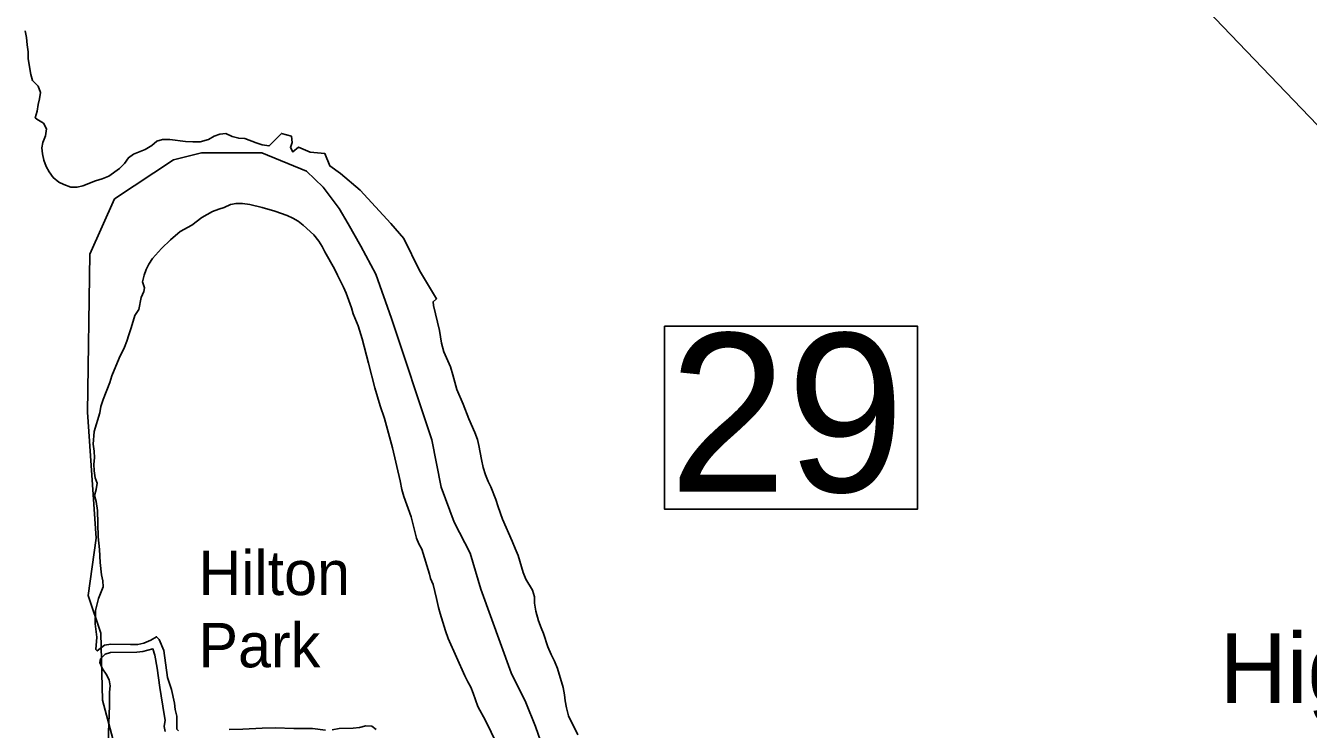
# Model space of a CAD drawing. Extents: x 1945482 to 2853149, y 66427 to 1015778.
# Drawn here: x 2317928 to 2321253, y 188516 to 190339 of the extents above; entities that cross this region are included whole.
import ezdxf

# ---------------------------------------------------------------- set-up
doc = ezdxf.new("R2010")
doc.units = 0
for name, color, linetype in [('Old_Level_19', 7, 'Continuous'), ('Old_Level_31', 7, 'Continuous'), ('Old_Level_48', 7, 'Continuous'), ('Old_Level_49', 7, 'Continuous'), ('Old_Level_56', 7, 'Continuous'), ('Old_Level_60', 7, 'Continuous'), ('Old_Level_9', 7, 'Continuous')]:
    doc.layers.add(name, color=color, linetype=linetype)

msp = doc.modelspace()

# ---------------------------------------------------------------- linework, layer by layer
at = {"layer": 'Old_Level_31'}
msp.add_lwpolyline([(2319584, 189560.5), (2320239.8, 189560.5), (2320239.8, 189086.6), (2319584, 189086.6)], close=True, dxfattribs=at)
at = {"layer": 'Old_Level_48'}
for points in [[(2317989.2, 186500.3), (2317987.1, 186775.2), (2318022.2, 187031.4), (2317993.3, 187312.5), (2318018.1, 187527.5), (2318092.5, 187707.3), (2318112.7, 187811), (2318144.1, 188046.3), (2318179.2, 188201.3), (2318181.3, 188391.4), (2318127.6, 188591.9), (2318123.4, 188765.5), (2318090.4, 188862.7), (2318111.1, 189011.5), (2318088.3, 189338), (2318094.5, 189747.3), (2318158.6, 189889.9), (2318311.4, 189991.1), (2318383.7, 190009.7)], [(2318383.7, 190009.7), (2318540.7, 190009.7), (2318656.4, 189962.2), (2318699.8, 189920.9), (2318741.3, 189865.1), (2318763.8, 189825.8), (2318796.9, 189767.9), (2318835.7, 189694.9), (2318876.2, 189580.4), (2318912.5, 189471.8), (2318944.4, 189375.1), (2318980.7, 189266.5), (2319005.5, 189143.7), (2319038.6, 189052.8), (2319080.4, 188972.3), (2319108.1, 188879.4), (2319186.7, 188662.5)], [(2319186.7, 188662.5), (2319224.5, 188585.7), (2319249.3, 188523.7), (2319281.9, 188432.2)]]:
    msp.add_lwpolyline(points, dxfattribs=at)
at = {"layer": 'Old_Level_49'}
for points in [[(2317989.2, 186500.3), (2317987.1, 186775.2), (2318022.2, 187031.4), (2317993.3, 187312.5), (2318018.1, 187527.5), (2318092.5, 187707.3), (2318112.7, 187811), (2318144.1, 188046.3), (2318179.2, 188201.3), (2318181.3, 188391.4), (2318127.6, 188591.9), (2318123.4, 188765.5), (2318090.4, 188862.7), (2318111.1, 189011.5), (2318088.3, 189338), (2318094.5, 189747.3), (2318158.6, 189889.9), (2318311.4, 189991.1), (2318383.7, 190009.7)], [(2318383.7, 190009.7), (2318540.7, 190009.7), (2318656.4, 189962.2), (2318699.8, 189920.9), (2318741.3, 189865.1), (2318763.8, 189825.8), (2318796.9, 189767.9), (2318835.7, 189694.9), (2318876.2, 189580.4), (2318912.5, 189471.8), (2318944.4, 189375.1), (2318980.7, 189266.5), (2319005.5, 189143.7), (2319038.6, 189052.8), (2319080.4, 188972.3), (2319108.1, 188879.4), (2319186.7, 188662.5)], [(2319186.7, 188662.5), (2319224.5, 188585.7), (2319249.3, 188523.7), (2319281.9, 188432.2)]]:
    msp.add_lwpolyline(points, dxfattribs=at)
at = {"layer": 'Old_Level_56'}
msp.add_lwpolyline([(2322518.1, 188787.6), (2320726, 190655.5), (2321161.7, 192135.8), (2321162.4, 192138.3)], dxfattribs=at)
at = {"layer": 'Old_Level_60'}
for points in [[(2317975.5, 189990.3), (2317971.7, 190006.6), (2317970.5, 190022.2), (2317973, 190036.2), (2317980, 190053.9), (2317982, 190071.9), (2317974.5, 190086.1), (2317957.5, 190096.6), (2317953.2, 190100.2), (2317958.5, 190117.7), (2317960.7, 190134.6), (2317964.5, 190149.2), (2317966.7, 190165.8), (2317961, 190181.9), (2317946, 190197), (2317942, 190212), (2317935, 190253.1), (2317934.5, 190270.8), (2317932.7, 190288.8), (2317930.2, 190308.4), (2317926.7, 190325.6)], [(2317975.5, 189990.3), (2317981.5, 189974.2), (2317989.2, 189960), (2318000, 189945.3), (2318014, 189933.8), (2318027.5, 189927.3), (2318045.5, 189920.8), (2318061.7, 189920.6), (2318076.5, 189924.3), (2318109, 189937.1), (2318126.5, 189942.5), (2318144, 189949.3), (2318171.5, 189968.8), (2318184.7, 189981.5), (2318194.7, 189996.8), (2318208, 190005.6), (2318238, 190018.5), (2318255, 190028.6), (2318268, 190039.7), (2318283, 190043.7), (2318302, 190043.6), (2318342.2, 190039), (2318361.5, 190037.8), (2318380.5, 190038.2), (2318402.5, 190043.9), (2318417.2, 190052.3), (2318431.5, 190057.6), (2318447, 190059.8), (2318463.5, 190051.7), (2318480.5, 190047.4), (2318496.2, 190046.5), (2318526, 190035.1), (2318541.7, 190030.3), (2318559.2, 190027.2), (2318591, 190059.7), (2318617, 190052.6), (2318619, 190036.4), (2318614.7, 190023.2), (2318621.2, 190012), (2318635.2, 190024.2), (2318665.7, 190011), (2318703.5, 190008), (2318716.5, 189975.5), (2318744.7, 189956.2), (2318795.5, 189912.5), (2318874.5, 189826.2), (2318908.2, 189787.6), (2318949.2, 189704.4), (2318993.5, 189631.7), (2318984.2, 189623.9), (2318985, 189614.4), (2319000.7, 189549.4), (2319006, 189516.4), (2319012, 189494.2), (2319029, 189454.8), (2319035.7, 189434.5), (2319045.7, 189396.2), (2319062.5, 189358.8), (2319077, 189320.8), (2319092.5, 189284.8), (2319099, 189266.7), (2319103, 189251.5), (2319109.5, 189215), (2319114.2, 189194.6), (2319120, 189175.9), (2319127.2, 189158), (2319134, 189144.3), (2319147, 189111.7), (2319153, 189092.3), (2319164.5, 189060.7), (2319189.5, 189004), (2319196.7, 188984.6), (2319204.5, 188966.8), (2319218, 188922.3), (2319224.5, 188905.1), (2319242.2, 188877), (2319247, 188859.2), (2319247.5, 188842.7), (2319250.7, 188822.1), (2319257.2, 188797.1), (2319264, 188778.9), (2319270.5, 188764.5), (2319282, 188729.8), (2319290.2, 188710.1)], [(2318773, 189607.8), (2318758.7, 189646), (2318752, 189661.8), (2318736.5, 189692.6), (2318729.2, 189708.9), (2318703.7, 189753), (2318697.2, 189766.6), (2318688.5, 189781), (2318675.5, 189797.5), (2318648, 189822.5), (2318635, 189832.4), (2318621.2, 189840.5), (2318606.5, 189847.1), (2318574.2, 189858.6), (2318541, 189867.9), (2318509, 189875.8), (2318490.2, 189878.4), (2318473.7, 189878.6), (2318459, 189875.3), (2318443.2, 189868.1), (2318428.7, 189863.6), (2318412.5, 189857.1), (2318385.2, 189841.7), (2318359, 189822.3), (2318328.7, 189805.6), (2318303.5, 189784.3), (2318280.2, 189761.5), (2318257, 189735.9), (2318247.5, 189721.1), (2318241, 189706.9)], [(2318110, 188723), (2318113.2, 188755.4), (2318108.2, 188789.8), (2318109.5, 188824), (2318117.2, 188855.4), (2318129.2, 188885.2), (2318128.5, 188901.2), (2318125.2, 188916.7), (2318121.2, 188948.7), (2318120, 188982.5), (2318116.5, 189015.3), (2318114.7, 189082.8), (2318111.5, 189106.1), (2318107, 189121.9), (2318111.2, 189137.2), (2318114, 189153.7), (2318108.7, 189167.9), (2318106, 189186.1), (2318105, 189202.8), (2318106.5, 189219.8), (2318105.5, 189237.2), (2318103.2, 189254.5), (2318105.7, 189288), (2318120.5, 189336), (2318123, 189352.1), (2318129.2, 189370.4), (2318146.7, 189415), (2318151.5, 189432.2), (2318170.5, 189477.6), (2318184.2, 189506), (2318191, 189521.8), (2318195.5, 189538.4), (2318201.7, 189556.3), (2318211, 189587.8), (2318221.5, 189603.3), (2318228, 189634.7), (2318235, 189650.1), (2318236.5, 189659.5), (2318231.5, 189675.4), (2318235.5, 189692.5), (2318241, 189706.9)], [(2319149.5, 188478.9), (2319119.7, 188539.6), (2319100.2, 188575.3), (2319088.5, 188609.9), (2319082, 188625.3), (2319074, 188639.2), (2319066.2, 188654.8), (2319023.5, 188751.5), (2319016.5, 188771.2), (2319002.5, 188816.2), (2318998, 188831.9), (2318993.5, 188854.9), (2318984.2, 188891.7), (2318977.2, 188906.9), (2318974.7, 188918.4), (2318955, 188982.7), (2318947.7, 188997), (2318941.7, 189011.3), (2318927.5, 189066.5), (2318908.5, 189119.3), (2318903.2, 189137.6), (2318899, 189159.8), (2318879, 189245), (2318858.5, 189321.6), (2318847, 189354.4), (2318833, 189401.2), (2318817.2, 189464.8), (2318800.2, 189527.9), (2318790.5, 189561), (2318777.5, 189592.9), (2318773, 189607.8)], [(2318110, 188723), (2318114, 188719.3), (2318133, 188734.3), (2318149.2, 188737.1), (2318200.2, 188735.9), (2318219, 188736.4), (2318234.7, 188739.7), (2318253, 188747.4), (2318267.5, 188756.2), (2318274.5, 188749.3), (2318286.5, 188720.6), (2318296.2, 188650.7), (2318306, 188619.4), (2318313.7, 188583.9), (2318316.2, 188567.8), (2318320, 188550.7), (2318320.5, 188517), (2318324.7, 188512.4)], [(2318290, 188510.8), (2318287, 188523.3), (2318289.7, 188539.7), (2318287.7, 188555.1), (2318276, 188624.5), (2318269, 188675.2), (2318263, 188708.5), (2318258, 188724.6), (2318231.7, 188718.1), (2318216.2, 188715.9), (2318148.2, 188715.1), (2318134, 188710.8), (2318122, 188699.3)], [(2318195.7, 188161.3), (2318195, 188176.8), (2318198.5, 188209.7), (2318196.7, 188264), (2318195.5, 188280.8), (2318183, 188340.3), (2318180, 188357.9), (2318175, 188374.6), (2318166.2, 188396.4), (2318157, 188408.4), (2318151.5, 188425.5), (2318150, 188442.7), (2318143.7, 188476.8), (2318142.7, 188507.8), (2318145.5, 188578.5), (2318145.7, 188612.3), (2318147, 188628.7), (2318145, 188644.5), (2318136.7, 188659), (2318127.2, 188672.8), (2318120.5, 188689.3), (2318122, 188699.3)], [(2319290.2, 188710.1), (2319299.2, 188693), (2319306.7, 188674.2), (2319321.5, 188625.1), (2319325, 188605.7), (2319326.5, 188590.4), (2319330.2, 188571.9), (2319335.5, 188551.7), (2319359.7, 188501.9)], [(2318456.2, 188516.3), (2318491.5, 188517.2), (2318541.5, 188519.8), (2318575.5, 188520.1), (2318623.2, 188518.5), (2318671.7, 188518.2), (2318705.2, 188514.1)], [(2318722.7, 188515.4), (2318741, 188518.1), (2318777.5, 188519.2), (2318793.2, 188521.4), (2318810, 188525.8), (2318825.5, 188524.9), (2318836.7, 188515.8)]]:
    msp.add_lwpolyline(points, dxfattribs=at)

# ---------------------------------------------------------------- texts
at = {"layer": 'Old_Level_19'}
for s, p in [('Hilton', (2318376.4, 188864)), ('Park', (2318376.4, 188677))]:
    msp.add_text(s, height=114.83, dxfattribs=at).set_placement(p)
at = {"layer": 'Old_Level_31'}
msp.add_text('29', height=410.1, dxfattribs=at).set_placement((2319595.7, 189131.6))
at = {"layer": 'Old_Level_9'}
msp.add_text('Hightsville', height=180.446, dxfattribs=at).set_placement((2321022.8, 188584.5))

doc.saveas('drawing.dxf')
